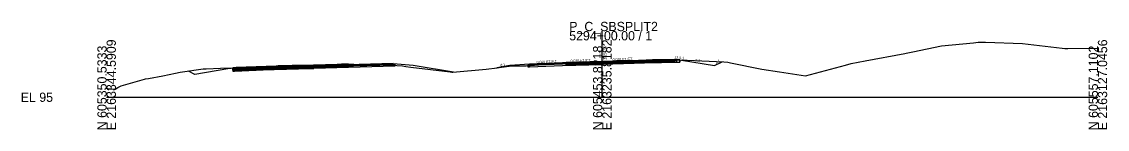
# Model space of a CAD drawing. Extents: x -26 to 1303, y -10 to 12033.
# Drawn here: x -25.7 to 302.8, y 7490.3 to 7522.8 of the extents above; entities that cross this region are included whole.
import ezdxf

# ---------------------------------------------------------------- set-up
doc = ezdxf.new("R2010")
doc.units = 0
for name, color, linetype in [('RD_GPK_XS_Cell', 7, 'Continuous'), ('RD_XS_Base', 7, 'Continuous'), ('RD_XS_ExGround', 7, 'Continuous'), ('RD_XS_ExPaveRet', 7, 'Continuous'), ('RD_XS_Greenside', 7, 'Continuous'), ('RD_XS_Pave', 7, 'Continuous'), ('RD_XS_PaveOvlay_CP', 7, 'Continuous'), ('RD_XS_TieSlope', 7, 'Continuous'), ('RD_XS_TX_Elev_EX', 7, 'Continuous'), ('RD_XS_TX_Elev_PR', 7, 'Continuous'), ('RD_XS_TX_ShdSlope', 7, 'Continuous'), ('RD_XS_TX_Slope', 7, 'Continuous')]:
    doc.layers.add(name, color=color, linetype=linetype)

msp = doc.modelspace()

# ---------------------------------------------------------------- linework, layer by layer
at = {"layer": 'RD_GPK_XS_Cell'}
for p, q in [((150, 7500), (150, 7520)), ((0, 7500), (150, 7500)), ((150, 7500), (300, 7500))]:
    msp.add_line(p, q, dxfattribs=at)
at = {"layer": 'RD_XS_Base'}
for p, q in [((150, 7510.45), (138, 7510.11)), ((150, 7510.45), (172, 7511.06)), ((150, 7509.95), (150, 7510.61)), ((150, 7510.61), (150, 7510.61)), ((150, 7510.61), (150, 7510.61)), ((150, 7510.61), (150, 7510.45)), ((172.5, 7510.58), (150, 7509.95)), ((150, 7510.45), (150, 7510.45)), ((150, 7509.95), (150, 7510.45)), ((150, 7510.45), (150, 7510.45)), ((150, 7510.45), (150, 7510.45)), ((162, 7510.78), (162, 7510.78)), ((162, 7510.78), (162, 7510.78)), ((162, 7510.28), (162, 7510.28)), ((162, 7510.28), (162, 7510.28)), ((172, 7511.06), (172, 7511.06)), ((172.5, 7511.08), (172.5, 7510.58)), ((172.5, 7511.04), (172.5, 7511.04)), ((38.68, 7508.43), (38.24, 7508.41)), ((38.24, 7508.41), (38.24, 7508.36)), ((38.24, 7508.36), (38.24, 7507.91)), ((38.24, 7507.91), (38.68, 7507.93)), ((38.74, 7508.43), (38.68, 7508.43)), ((38.68, 7507.93), (38.74, 7507.93)), ((49.61, 7508.86), (38.74, 7508.43)), ((38.74, 7507.93), (49.61, 7508.36)), ((50.74, 7508.91), (49.61, 7508.86)), ((49.61, 7508.36), (50.74, 7508.41)), ((61.78, 7509.2), (50.74, 7508.91)), ((50.74, 7508.41), (61.78, 7508.7)), ((62.74, 7509.22), (61.78, 7509.2)), ((61.78, 7508.7), (62.74, 7508.72)), ((62.74, 7509.22), (87.24, 7509.86)), ((62.74, 7508.72), (62.74, 7509.38)), ((62.74, 7509.38), (62.74, 7509.38)), ((62.74, 7509.38), (62.74, 7509.38)), ((62.74, 7509.38), (62.74, 7509.22)), ((87.24, 7509.36), (62.74, 7508.72)), ((62.74, 7509.22), (62.74, 7509.22)), ((62.74, 7508.72), (62.74, 7509.22)), ((62.74, 7509.22), (62.74, 7509.22)), ((62.74, 7509.22), (62.74, 7509.22)), ((62.74, 7508.72), (62.74, 7508.72)), ((86.74, 7509.84), (86.74, 7509.84)), ((86.74, 7509.84), (86.74, 7509.84)), ((86.74, 7509.84), (86.74, 7509.84)), ((86.74, 7509.34), (86.74, 7509.34)), ((86.74, 7509.34), (86.74, 7509.34)), ((87.24, 7509.86), (87.24, 7509.36)), ((87.24, 7509.82), (87.24, 7509.82)), ((128, 7509.71), (127.5, 7509.69)), ((127.5, 7509.69), (127.5, 7509.69)), ((127.5, 7509.69), (127.5, 7509.19)), ((127.5, 7509.19), (128, 7509.21)), ((138, 7510.11), (128, 7509.71)), ((128, 7509.71), (128, 7509.71)), ((128, 7509.21), (138, 7509.61)), ((128, 7509.21), (128, 7509.21)), ((136, 7510.03), (136, 7510.03)), ((136, 7509.53), (136, 7509.53)), ((138, 7509.61), (150, 7509.95)), ((150, 7509.95), (150, 7509.95))]:
    msp.add_line(p, q, dxfattribs=at)
at = {"layer": 'RD_XS_ExGround'}
msp.add_lwpolyline([(0, 7502.7), (0.65, 7502.52), (1.08, 7502.52), (2.63, 7502.48), (3.42, 7502.91), (4.39, 7503.47), (11.44, 7505.46), (11.76, 7505.55), (12.69, 7505.71), (16.98, 7506.5), (20.83, 7507.29), (22.27, 7507.58), (29.19, 7508.57), (29.75, 7508.57), (30.12, 7508.59), (34.51, 7508.76), (38.15, 7508.9), (39.16, 7508.95), (51.94, 7509.46), (53.69, 7509.5), (56.52, 7509.56), (57.76, 7509.59), (60.97, 7509.64), (61.12, 7509.64), (69.8, 7509.94), (73.2, 7510.05), (74.86, 7510.01), (77.02, 7509.9), (85.63, 7509.72), (86.12, 7509.7), (89.56, 7509.46), (90.56, 7509.32), (92.03, 7509.13), (104.01, 7507.65), (104.44, 7507.6), (104.75, 7507.63), (114.84, 7508.5), (118.17, 7508.91), (119.55, 7509.06), (122.68, 7509.45), (123.34, 7509.46), (123.69, 7509.46), (126.93, 7509.5), (130.75, 7509.8), (132.03, 7509.91), (139.08, 7510.49), (143.05, 7510.61), (153.11, 7510.86), (154.34, 7510.98), (161.41, 7511.16), (165.21, 7511.29), (167.96, 7511.29), (173.44, 7511.34), (186.84, 7510.66), (187.97, 7510.6), (188.86, 7510.43), (198.28, 7508.52), (203.63, 7507.69), (211.53, 7506.49), (223.59, 7509.73), (225.35, 7510.21), (229.59, 7511.01), (241.58, 7513.25), (241.96, 7513.28), (243.98, 7513.74), (252.62, 7515.54), (262.35, 7516.5), (263.81, 7516.63), (265.97, 7516.62), (277.16, 7516.26), (289.17, 7514.85), (290.03, 7514.75), (290.87, 7514.76), (300, 7514.81)], dxfattribs=at)
at = {"layer": 'RD_XS_ExPaveRet'}
for points in [[(173.44, 7511.34), (173.44, 7511.34), (173.44, 7510.59), (173.44, 7510.59), (167.96, 7510.54), (167.96, 7510.54), (165.21, 7510.54), (165.21, 7510.54), (165.21, 7510.54), (161.41, 7510.41), (161.41, 7510.41), (154.34, 7510.23), (154.34, 7510.23), (153.11, 7510.11), (153.11, 7510.11), (143.05, 7509.86), (143.05, 7509.86), (139.08, 7509.74), (139.08, 7509.74), (139.08, 7510.49), (139.08, 7510.49), (139.08, 7510.49), (143.05, 7510.61), (143.05, 7510.61), (153.11, 7510.86), (153.11, 7510.86), (154.34, 7510.98), (154.34, 7510.98), (161.41, 7511.16), (161.41, 7511.16), (165.21, 7511.29), (165.21, 7511.29), (165.21, 7511.29), (167.96, 7511.29), (167.96, 7511.29), (173.44, 7511.34), (173.44, 7511.34)], [(167.96, 7511.29), (165.21, 7511.29), (161.41, 7511.16), (154.34, 7510.98), (153.11, 7510.86), (143.05, 7510.61), (139.08, 7510.49), (139.08, 7510.49), (139.08, 7509.74), (139.08, 7509.74), (143.05, 7509.86), (153.11, 7510.11), (154.34, 7510.23), (161.41, 7510.41), (165.21, 7510.54), (167.96, 7510.54), (173.44, 7510.59), (173.44, 7511.34), (167.96, 7511.29)], [(71.11, 7509.99), (73.2, 7510.05), (73.2, 7509.5), (73.2, 7509.3), (71.11, 7509.24), (69.8, 7509.19), (62.61, 7508.94), (61.12, 7508.89), (61.11, 7508.89), (60.97, 7508.89), (58.28, 7508.85), (57.76, 7508.84), (56.79, 7508.82), (56.52, 7508.81), (56.15, 7508.8), (53.69, 7508.75), (52.6, 7508.73), (51.94, 7508.71), (51.31, 7508.69), (39.16, 7508.2), (38.15, 7508.15), (38.15, 7508.15), (38.15, 7508.24), (38.15, 7508.9), (38.15, 7508.9), (39.16, 7508.95), (51.31, 7509.44), (51.94, 7509.46), (52.6, 7509.48), (53.69, 7509.5), (56.15, 7509.55), (56.52, 7509.56), (56.79, 7509.57), (57.76, 7509.59), (58.28, 7509.6), (60.97, 7509.64), (61.11, 7509.64), (61.12, 7509.64), (62.61, 7509.69), (69.8, 7509.94), (71.11, 7509.99)], [(69.8, 7509.94), (62.61, 7509.69), (61.12, 7509.64), (61.11, 7509.64), (60.97, 7509.64), (58.28, 7509.6), (57.76, 7509.59), (56.79, 7509.57), (56.52, 7509.56), (56.15, 7509.55), (53.69, 7509.5), (52.6, 7509.48), (51.94, 7509.46), (51.31, 7509.44), (39.16, 7508.95), (38.15, 7508.9), (38.15, 7508.9), (38.15, 7508.24), (38.15, 7508.15), (38.15, 7508.15), (39.16, 7508.2), (51.31, 7508.69), (51.94, 7508.71), (52.6, 7508.73), (53.69, 7508.75), (56.15, 7508.8), (56.52, 7508.81), (56.79, 7508.82), (57.76, 7508.84), (58.28, 7508.85), (60.97, 7508.89), (61.11, 7508.89), (61.12, 7508.89), (62.61, 7508.94), (69.8, 7509.19), (71.11, 7509.24), (73.2, 7509.3), (73.2, 7509.5), (73.2, 7510.05), (71.11, 7509.99), (69.8, 7509.94)]]:
    msp.add_lwpolyline(points, dxfattribs=at)
at = {"layer": 'RD_XS_Greenside'}
for p, q in [((174, 7511.22), (184, 7509.55)), ((184, 7509.55), (186.27, 7510.69)), ((26.73, 7506.92), (24.75, 7507.91)), ((36.73, 7508.59), (26.73, 7506.92)), ((92.74, 7509.68), (104.94, 7507.65)), ((122, 7509.55), (118.11, 7508.9))]:
    msp.add_line(p, q, dxfattribs=at)
at = {"layer": 'RD_XS_Pave'}
for p, q in [((138, 7510.43), (128, 7510.03)), ((128, 7509.87), (138, 7510.27)), ((138, 7510.27), (128, 7509.87)), ((136, 7510.35), (136, 7510.35)), ((150, 7510.76), (138, 7510.43)), ((138, 7510.27), (150, 7510.61)), ((150, 7510.61), (138, 7510.27)), ((138, 7510.11), (150, 7510.45)), ((172, 7511.38), (150, 7510.76)), ((172, 7511.22), (150, 7510.61)), ((150, 7510.61), (172, 7511.22)), ((150, 7510.45), (172.5, 7511.08)), ((150, 7510.76), (150, 7510.76)), ((150, 7510.61), (150, 7510.61)), ((150, 7510.61), (150, 7510.61)), ((150, 7510.61), (150, 7510.45)), ((150, 7510.61), (150, 7510.61)), ((150, 7510.45), (150, 7510.61)), ((150, 7510.61), (150, 7510.61)), ((150, 7510.61), (150, 7510.61)), ((150, 7510.45), (150, 7510.45)), ((150, 7510.45), (150, 7510.45)), ((162, 7511.1), (162, 7511.1)), ((162, 7511.1), (162, 7511.1)), ((162, 7510.94), (162, 7510.94)), ((162, 7510.94), (162, 7510.94)), ((162, 7510.94), (162, 7510.94)), ((162, 7510.94), (162, 7510.94)), ((162, 7510.78), (162, 7510.78)), ((162, 7510.78), (162, 7510.78)), ((172, 7511.22), (172, 7511.38)), ((172, 7511.38), (172, 7511.38)), ((172, 7511.06), (172, 7511.22)), ((172, 7511.22), (172, 7511.22)), ((49.61, 7509.18), (38.74, 7508.75)), ((38.74, 7508.59), (49.61, 7509.02)), ((49.61, 7509.02), (38.74, 7508.59)), ((38.74, 7508.43), (49.61, 7508.86)), ((38.74, 7508.75), (38.74, 7508.73)), ((38.74, 7508.73), (38.74, 7508.59)), ((38.74, 7508.59), (38.74, 7508.57)), ((38.74, 7508.57), (38.74, 7508.43)), ((50.74, 7509.23), (49.61, 7509.18)), ((49.61, 7509.02), (50.74, 7509.07)), ((50.74, 7509.07), (49.61, 7509.02)), ((49.61, 7508.86), (50.74, 7508.91)), ((61.78, 7509.51), (50.74, 7509.23)), ((50.74, 7509.07), (61.78, 7509.35)), ((61.78, 7509.35), (50.74, 7509.07)), ((50.74, 7508.91), (61.78, 7509.2)), ((62.74, 7509.54), (61.78, 7509.51)), ((61.78, 7509.35), (62.74, 7509.38)), ((62.74, 7509.38), (61.78, 7509.35)), ((61.78, 7509.2), (62.74, 7509.22)), ((86.74, 7510.16), (62.74, 7509.54)), ((86.74, 7510), (62.74, 7509.38)), ((62.74, 7509.38), (86.74, 7510)), ((62.74, 7509.22), (86.74, 7509.84)), ((62.74, 7509.54), (62.74, 7509.54)), ((62.74, 7509.38), (62.74, 7509.38)), ((62.74, 7509.38), (62.74, 7509.38)), ((62.74, 7509.38), (62.74, 7509.22)), ((62.74, 7509.38), (62.74, 7509.38)), ((62.74, 7509.22), (62.74, 7509.38)), ((62.74, 7509.38), (62.74, 7509.38)), ((62.74, 7509.38), (62.74, 7509.38)), ((62.74, 7509.22), (62.74, 7509.22)), ((62.74, 7509.22), (62.74, 7509.22)), ((86.74, 7510), (86.74, 7510.16)), ((86.74, 7510.16), (86.74, 7510.16)), ((86.74, 7510.16), (86.74, 7510.16)), ((86.74, 7510.16), (86.74, 7510.16)), ((86.74, 7509.84), (86.74, 7510)), ((86.74, 7510), (86.74, 7510)), ((86.74, 7510), (86.74, 7510)), ((86.74, 7510), (86.74, 7510)), ((86.74, 7510), (86.74, 7510)), ((86.74, 7510), (86.74, 7510)), ((86.74, 7509.84), (86.74, 7509.84)), ((86.74, 7509.84), (86.74, 7509.84)), ((128, 7509.71), (138, 7510.11)), ((128, 7510.03), (128, 7510.03)), ((128, 7510.03), (128, 7509.87)), ((128, 7509.87), (128, 7509.87)), ((128, 7509.87), (128, 7509.71)), ((136, 7510.19), (136, 7510.19)), ((136, 7510.19), (136, 7510.19)), ((136, 7510.03), (136, 7510.03))]:
    msp.add_line(p, q, dxfattribs=at)
at = {"layer": 'RD_XS_PaveOvlay_CP'}
for p, q in [((138, 7510.43), (128, 7510.03)), ((136, 7510.35), (136, 7510.35)), ((150, 7510.76), (138, 7510.43)), ((172, 7511.38), (150, 7510.76)), ((150, 7510.76), (150, 7510.76)), ((162, 7511.1), (162, 7511.1)), ((162, 7511.1), (162, 7511.1)), ((49.61, 7509.18), (38.74, 7508.75)), ((50.74, 7509.23), (49.61, 7509.18)), ((61.78, 7509.51), (50.74, 7509.23)), ((62.74, 7509.54), (61.78, 7509.51)), ((86.74, 7510.16), (62.74, 7509.54)), ((62.74, 7509.54), (62.74, 7509.54)), ((86.74, 7510.16), (86.74, 7510.16)), ((86.74, 7510.16), (86.74, 7510.16))]:
    msp.add_line(p, q, dxfattribs=at)
at = {"layer": 'RD_XS_TieSlope'}
for p, q in [((172, 7511.38), (174, 7511.22)), ((38.74, 7508.75), (36.73, 7508.59)), ((86.74, 7510.16), (92.74, 7509.68)), ((128, 7510.03), (122, 7509.55))]:
    msp.add_line(p, q, dxfattribs=at)

# ---------------------------------------------------------------- texts
at = {"layer": 'RD_GPK_XS_Cell'}
for s, p in [('5294+00.00 / 1', (140, 7517.2)), ('P_C_SBSPLIT2', (140, 7520)), ('EL 95', (-26, 7498.6))]:
    msp.add_text(s, height=2.8, dxfattribs=at).set_placement(p)
for s, p in [('E 2163344.5909', (2.8, 7490)), ('E 2163235.8182', (152.8, 7490)), ('E 2163127.0456', (302.8, 7490)), ('N 605350.5333', (0, 7490)), ('N 605453.8218', (150, 7490)), ('N 605557.1102', (300, 7490))]:
    msp.add_text(s, height=2.8, rotation=90, dxfattribs=at).set_placement(p)
at = {"layer": 'RD_XS_TX_Elev_EX'}
msp.add_text('105.78', height=0.6, rotation=90, dxfattribs=at).set_placement((149.66, 7511.64))
at = {"layer": 'RD_XS_TX_Elev_PR'}
msp.add_text('105.76', height=1, rotation=90, dxfattribs=at).set_placement((151.32, 7511.22))
at = {"layer": 'RD_XS_TX_ShdSlope'}
msp.add_text('12.5:1', height=0.75, rotation=355.4261, dxfattribs=at).set_placement((171.84, 7511.69))
at = {"layer": 'RD_XS_TX_Slope'}
for s, rotation, p in [('0.040 FT./FT.', 2.2906, (130.15, 7510.24)), ('0.030 FT./FT.', 1.7184, (140.42, 7510.66)), ('0.030 FT./FT.', 1.7184, (153.16, 7511.03)), ('6:1', 350.5358, (178.13, 7510.91)), ('2:1', 26.5651, (184.41, 7510.17)), ('6:1', 9.4623, (119.22, 7509.31))]:
    msp.add_text(s, height=0.75, rotation=rotation, dxfattribs=at).set_placement(p)

doc.saveas('drawing.dxf')
